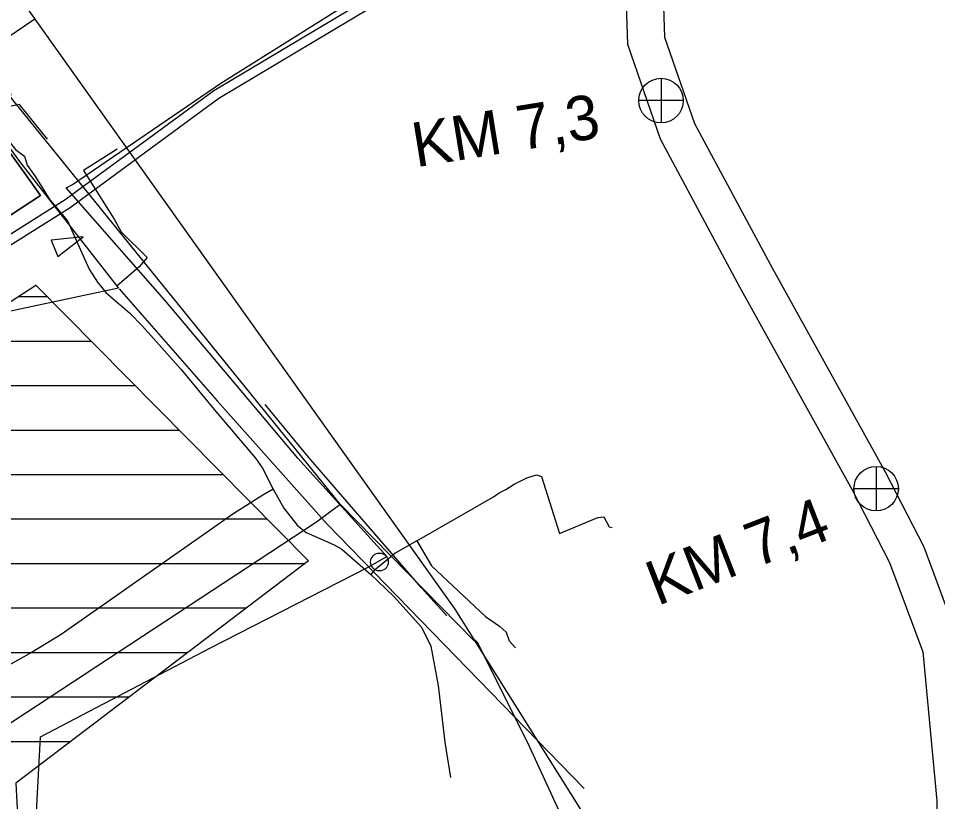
# Model space of a CAD drawing. Extents: x -478232 to -472707, y -1118753 to -1113967.
# Drawn here: x -476775.2 to -476568.7, y -1115764.3 to -1115588.3 of the extents above; entities that cross this region are included whole.
import ezdxf

# ---------------------------------------------------------------- set-up
doc = ezdxf.new("R2010")
doc.units = 0
for name, color, linetype in [('cesty', 7, 'Continuous'), ('el vedeni _VN', 7, 'Continuous'), ('el vedeni_NN', 7, 'Continuous'), ('meliorace', 7, 'Continuous'), ('nesmenovane pozemky', 7, 'Continuous'), ('ObPÚ', 7, 'Continuous'), ('plyn_ntl', 7, 'Continuous'), ('staničení toku', 7, 'Continuous'), ('telekomunikační kabel_O2', 7, 'Continuous'), ('VAK_kanalizace', 7, 'Continuous'), ('VAK_vodovod', 7, 'Continuous'), ('VAK_vodovod_přípojky', 7, 'Continuous'), ('vodní plochy', 7, 'Continuous'), ('Vrstevnice_vedlejsi', 7, 'Continuous')]:
    doc.layers.add(name, color=color, linetype=linetype)

msp = doc.modelspace()

# ---------------------------------------------------------------- linework, layer by layer
at = {"layer": 'cesty'}
msp.add_line((-476767.802, -1115638.116), (-476766.323, -1115641.832), dxfattribs=at)
msp.add_lwpolyline([(-476766.323, -1115641.832), (-476760.608, -1115637.405), (-476767.802, -1115638.116)], dxfattribs=at)
msp.add_circle((-476694.085, -1115710.466), 2, dxfattribs=at)
at = {"layer": 'el vedeni _VN'}
msp.add_lwpolyline([(-476752.99, -1115617.645), (-476760.59, -1115622.439), (-476753.68, -1115633.389), (-476752.07, -1115636.279), (-476746.28, -1115641.999), (-476748.07, -1115644.089), (-476753.11, -1115648.49), (-476752.713, -1115648.935)], dxfattribs=at)
at = {"layer": 'el vedeni_NN'}
for points in [[(-476842.746, -1115543.945), (-476826.67, -1115539.41), (-476812.925, -1115568.597), (-476794.56, -1115593.64), (-476774.96, -1115620.42), (-476752.697, -1115648.952), (-476789.33, -1115656.72), (-476825.27, -1115681.966), (-476857.812, -1115702.761), (-476874.3, -1115755.055)], [(-476752.574, -1115649.093), (-476730.57, -1115674.25), (-476705.81, -1115701.99), (-476648.091, -1115761.403)]]:
    msp.add_lwpolyline(points, dxfattribs=at)
at = {"layer": 'meliorace'}
for p, q in [((-476775.177, -1115650.794), (-476768.78, -1115650.794)), ((-476790.636, -1115660.794), (-476758.887, -1115660.794)), ((-476806.095, -1115670.794), (-476748.994, -1115670.794)), ((-476821.943, -1115680.794), (-476739.101, -1115680.794)), ((-476838.134, -1115690.794), (-476729.208, -1115690.794)), ((-476854.326, -1115700.794), (-476719.315, -1115700.794)), ((-476870.517, -1115710.794), (-476710.772, -1115710.794)), ((-476887.057, -1115720.794), (-476723.945, -1115720.794)), ((-476904.288, -1115730.794), (-476737.118, -1115730.794)), ((-476919.019, -1115740.794), (-476750.29, -1115740.794)), ((-476932.733, -1115750.794), (-476763.463, -1115750.794))]:
    msp.add_line(p, q, dxfattribs=at)
msp.add_lwpolyline([(-476813.359, -1115675.493), (-476771.276, -1115648.271), (-476710.001, -1115710.209), (-476775.799, -1115760.159), (-476774.472, -1115784.378), (-476739.301, -1115887.796), (-476708.136, -1115991.912), (-476722.792, -1115995.923), (-476695.35, -1116044.873), (-476818.693, -1116112.057)], dxfattribs=at)
at = {"layer": 'nesmenovane pozemky'}
for points in [[(-476792.25, -1115597.59), (-476773.71, -1115623.21), (-476770.21, -1115628.06), (-476787.44, -1115639.3)], [(-476787.44, -1115639.3), (-476770.21, -1115628.06), (-476773.71, -1115623.21), (-476792.25, -1115597.59)]]:
    msp.add_lwpolyline(points, dxfattribs=at)
at = {"layer": 'ObPÚ'}
msp.add_lwpolyline([(-476755.544, -1115798.967), (-476755.79, -1115797.97), (-476764.44, -1115799.55), (-476770.52, -1115780.17), (-476771.02, -1115765.24), (-476770.22, -1115749.72), (-476741.776, -1115734.824), (-476732.03, -1115729.72), (-476696.78, -1115711.69), (-476692.45, -1115709.23), (-476710.39, -1115689.36), (-476712.42, -1115687.12), (-476720, -1115678.12), (-476742.31, -1115651.59), (-476761.19, -1115630.08), (-476764.44, -1115626.38), (-476763.03, -1115625.58), (-476729.68, -1115602.85), (-476697.22, -1115582.39)], dxfattribs=at)
at = {"layer": 'plyn_ntl'}
for points in [[(-476768.62, -1115615.425), (-476774.967, -1115607.61), (-476777.83, -1115608.24), (-476776.827, -1115605.311), (-476785.143, -1115595.032), (-476786.55, -1115596.24), (-476786.97, -1115595.69), (-476787.43, -1115594.65), (-476786.145, -1115593.792), (-476796.003, -1115581.607), (-476800.611, -1115575.284), (-476799.879, -1115572.693), (-476800.947, -1115571.002), (-476803.485, -1115571.341), (-476826.742, -1115538.926), (-476844.672, -1115531.409), (-476847.418, -1115530.475)], [(-476678.906, -1115722.55), (-476684.652, -1115716.251), (-476709.926, -1115687.011), (-476719.738, -1115675.069)]]:
    msp.add_lwpolyline(points, dxfattribs=at)
at = {"layer": 'staničení toku'}
for p, q in [((-476630.813, -1115601.754), (-476630.813, -1115611.754)), ((-476625.813, -1115606.754), (-476635.813, -1115606.754)), ((-476582.486, -1115688.979), (-476582.486, -1115698.979)), ((-476577.486, -1115693.979), (-476587.486, -1115693.979))]:
    msp.add_line(p, q, dxfattribs=at)
for centre in [(-476630.813, -1115606.754), (-476582.486, -1115693.979)]:
    msp.add_circle(centre, 5, dxfattribs=at)
at = {"layer": 'telekomunikační kabel_O2'}
for points in [[(-476795.86, -1115590.93), (-476793.46, -1115592.37), (-476792.94, -1115594.42), (-476787.13, -1115602.51), (-476786.27, -1115604.1), (-476781.16, -1115611.21), (-476775.83, -1115617.77), (-476773.83, -1115619.24), (-476773.21, -1115621.26), (-476771.36, -1115623.91), (-476768.11, -1115629.05), (-476766.84, -1115630.54), (-476764.19, -1115633.77), (-476759.3, -1115644.62), (-476757.44, -1115647.57), (-476755.47, -1115649.96), (-476750.24, -1115654.43), (-476747.33, -1115657.43), (-476738.59, -1115667.17), (-476731.2, -1115676.2), (-476721.89, -1115687.13), (-476720.36, -1115689.36), (-476717.92, -1115694.08)], [(-476685.69, -1115705.74), (-476668.46, -1115695.81), (-476667.16, -1115694.95), (-476665.66, -1115694.15), (-476663.84, -1115692.93), (-476660.95, -1115691.56), (-476658.81, -1115690.9), (-476657.64, -1115691.22), (-476653.59, -1115704.04), (-476645.01, -1115700.43), (-476643.67, -1115700.34), (-476642.43, -1115702.52), (-476641.77, -1115702.7)], [(-476717.92, -1115694.08), (-476720.31, -1115695.41), (-476726.82, -1115699.56), (-476765.59, -1115726.76), (-476772.12, -1115730.76), (-476777.23, -1115733.55), (-476814.59, -1115755.33), (-476823.08, -1115763.59), (-476832.29, -1115773.13), (-476834.57, -1115777.72), (-476837.05, -1115781.43), (-476838.36, -1115783.59)], [(-476717.92, -1115694.08), (-476715.59, -1115698.34), (-476712.58, -1115702.18), (-476710.53, -1115703.8), (-476704.24, -1115706.58), (-476702.51, -1115707.57), (-476695.98, -1115713.3)], [(-476685.69, -1115705.74), (-476690.51, -1115708.46), (-476691.58, -1115709.41), (-476695.28, -1115712.34), (-476695.98, -1115713.3)], [(-476685.69, -1115705.74), (-476682.42, -1115711.33), (-476670.27, -1115722.69), (-476667.14, -1115724.87), (-476665.63, -1115726.21), (-476664.95, -1115728.18), (-476663.54, -1115729.78)], [(-476695.98, -1115713.3), (-476690.87, -1115718.25), (-476684.61, -1115725.07), (-476682.55, -1115729.41), (-476680.87, -1115738.2), (-476679.36, -1115750.92), (-476678.12, -1115758.87)]]:
    msp.add_lwpolyline(points, dxfattribs=at)
at = {"layer": 'VAK_kanalizace'}
for points in [[(-476596.91, -1115841.27), (-476639.491, -1115781.004), (-476677.085, -1115721.078), (-476807.031, -1115538.469)], [(-476894.404, -1115671.748), (-476771.514, -1115588.381)]]:
    msp.add_lwpolyline(points, dxfattribs=at)
at = {"layer": 'VAK_vodovod'}
for points in [[(-476672.829, -1115728.19), (-476702.929, -1115697.489), (-476776.53, -1115606.54), (-476784.5, -1115595.84), (-476802.579, -1115571.44), (-476814.96, -1115553.93), (-476816.319, -1115551.759), (-476816.39, -1115551.679), (-476816.539, -1115551.549)], [(-476597.42, -1115847.819), (-476597.5, -1115847.629), (-476609.099, -1115828.549), (-476636.19, -1115792.68), (-476641.09, -1115787.7), (-476646.199, -1115782.6), (-476646.3, -1115782.469), (-476660.829, -1115750.93), (-476672.039, -1115728.579), (-476672.619, -1115727.94), (-476672.81, -1115728.211), (-476672.829, -1115728.19)]]:
    msp.add_lwpolyline(points, dxfattribs=at)
at = {"layer": 'VAK_vodovod_přípojky'}
msp.add_lwpolyline([(-476702.929, -1115697.489), (-476703.01, -1115697.59), (-476708.23, -1115701.54), (-476836.062, -1115785.486)], dxfattribs=at)
at = {"layer": 'vodní plochy'}
for points in [[(-476638.113, -1115553.904), (-476643.882, -1115556.28), (-476692.746, -1115581.454), (-476731.259, -1115604.531), (-476764.657, -1115629.099), (-476802.386, -1115652.775), (-476819.266, -1115663.622), (-476873.466, -1115698.453), (-476876.962, -1115700.938), (-476893.934, -1115713.636)], [(-476818.184, -1115665.304), (-476801.314, -1115654.463), (-476763.531, -1115630.753), (-476730.149, -1115606.199), (-476691.774, -1115583.202), (-476643.042, -1115558.096), (-476638.192, -1115556.1)], [(-476638.918, -1115576.256), (-476638.355, -1115594.111), (-476631.011, -1115615.36), (-476613.159, -1115648.596), (-476587.847, -1115694.272), (-476579.484, -1115710.554), (-476572.024, -1115730.684), (-476568.86, -1115764.155), (-476569.538, -1115796.945), (-476573.154, -1115833.122), (-476573.38, -1115858.669), (-476569.313, -1115885.12)], [(-476561.038, -1115883.278), (-476564.915, -1115858.06), (-476564.699, -1115833.581), (-476561.088, -1115797.453), (-476560.393, -1115763.843), (-476563.707, -1115728.784), (-476571.729, -1115707.14), (-476580.384, -1115690.288), (-476605.733, -1115644.544), (-476623.238, -1115611.955), (-476629.941, -1115592.562), (-476630.454, -1115576.275)]]:
    msp.add_lwpolyline(points, dxfattribs=at)
at = {"layer": 'Vrstevnice_vedlejsi'}
for points in [[(-476765.232, -1115950.68), (-476768.635, -1115941.359), (-476771.601, -1115933.808), (-476774.129, -1115928.026), (-476776.22, -1115924.013), (-476777.972, -1115919.286), (-476779.386, -1115913.846), (-476780.463, -1115907.693), (-476783.231, -1115902.898), (-476787.693, -1115899.461), (-476793.846, -1115897.383), (-476799.718, -1115894.297), (-476805.309, -1115890.204), (-476810.617, -1115885.102), (-476816.831, -1115878.775), (-476823.951, -1115871.224), (-476831.975, -1115862.448), (-476838.218, -1115855.08), (-476842.677, -1115849.118), (-476845.355, -1115844.563), (-476849.062, -1115837.384), (-476853.798, -1115827.581), (-476859.563, -1115815.153), (-476863.515, -1115806.728), (-476865.653, -1115802.304), (-476865.978, -1115801.882), (-476866.162, -1115801.565), (-476866.206, -1115801.352), (-476866.111, -1115801.245), (-476866.068, -1115801.121), (-476866.077, -1115800.981), (-476866.139, -1115800.826), (-476867.724, -1115798.235), (-476870.834, -1115793.208), (-476875.467, -1115785.746), (-476879.116, -1115780.289), (-476881.782, -1115776.838), (-476883.464, -1115775.392), (-476886.105, -1115772.851), (-476889.705, -1115769.216), (-476894.264, -1115764.487), (-476898.706, -1115759.072), (-476903.029, -1115752.972), (-476907.235, -1115746.186), (-476910.642, -1115741.194), (-476913.25, -1115737.996), (-476915.059, -1115736.591), (-476916.37, -1115735.556), (-476917.182, -1115734.891), (-476917.495, -1115734.596), (-476917.73, -1115734.3), (-476917.886, -1115734.003), (-476917.963, -1115733.706), (-476918.084, -1115733.385), (-476918.249, -1115733.04), (-476918.458, -1115732.672), (-476919, -1115731.221), (-476919.876, -1115728.689), (-476921.085, -1115725.074), (-476922.197, -1115722.333), (-476923.212, -1115720.464), (-476924.13, -1115719.468), (-476925.018, -1115718.454), (-476925.874, -1115717.423), (-476926.701, -1115716.374), (-476927.413, -1115715.574), (-476928.011, -1115715.022), (-476928.496, -1115714.719), (-476928.752, -1115713.957), (-476928.779, -1115712.734), (-476928.578, -1115711.051), (-476928.475, -1115709.892), (-476928.472, -1115709.256), (-476928.569, -1115709.144), (-476928.659, -1115709.026), (-476928.742, -1115708.9), (-476928.819, -1115708.767), (-476929.107, -1115708.172), (-476929.607, -1115707.115), (-476930.318, -1115705.596), (-476930.876, -1115704.442), (-476931.281, -1115703.653), (-476931.531, -1115703.231), (-476931.893, -1115702.616), (-476932.367, -1115701.808), (-476932.951, -1115700.808), (-476933.519, -1115699.983), (-476934.071, -1115699.331), (-476934.606, -1115698.854), (-476935.124, -1115698.369), (-476935.624, -1115697.876), (-476936.106, -1115697.375), (-476936.698, -1115696.799), (-476937.4, -1115696.148), (-476938.212, -1115695.422), (-476938.943, -1115694.713), (-476939.594, -1115694.023)], [(-476760.309, -1115922.621), (-476760.619, -1115921.775), (-476760.878, -1115921.107), (-476761.089, -1115920.619), (-476761.25, -1115920.309), (-476761.996, -1115916.454), (-476763.326, -1115909.052), (-476765.241, -1115898.104), (-476768.872, -1115890.01), (-476774.22, -1115884.77), (-476781.284, -1115882.385), (-476786.446, -1115879.954), (-476789.707, -1115877.475), (-476791.066, -1115874.951), (-476792.814, -1115873.183), (-476794.951, -1115872.171), (-476797.475, -1115871.916), (-476802.154, -1115868.229), (-476808.987, -1115861.108), (-476817.975, -1115850.554), (-476824.428, -1115842.713), (-476828.348, -1115837.584), (-476829.735, -1115835.168), (-476830.854, -1115833.384), (-476831.706, -1115832.231), (-476832.291, -1115831.709), (-476832.904, -1115831.275), (-476833.544, -1115830.927), (-476834.212, -1115830.665), (-476834.845, -1115829.575), (-476835.443, -1115827.656), (-476836.005, -1115824.907), (-476836.546, -1115822.913), (-476837.067, -1115821.673), (-476837.567, -1115821.188), (-476838.198, -1115819.989), (-476838.961, -1115818.079), (-476839.855, -1115815.456), (-476840.607, -1115812.288), (-476841.217, -1115808.577), (-476841.685, -1115804.321), (-476842.285, -1115800.103), (-476843.015, -1115795.923), (-476843.876, -1115791.78), (-476846.033, -1115787.218), (-476849.486, -1115782.239), (-476854.234, -1115776.84), (-476859.483, -1115771.888), (-476865.232, -1115767.382), (-476871.482, -1115763.322), (-476875.748, -1115760.389), (-476878.03, -1115758.582), (-476878.328, -1115757.902), (-476878.568, -1115757.35), (-476878.75, -1115756.925), (-476878.875, -1115756.629), (-476879.002, -1115756.301), (-476879.132, -1115755.942), (-476879.265, -1115755.552), (-476879.374, -1115755.119), (-476879.458, -1115754.643), (-476879.519, -1115754.124), (-476880.12, -1115751.501), (-476881.261, -1115746.774), (-476882.942, -1115739.943), (-476884.416, -1115735.179), (-476885.681, -1115732.482), (-476886.738, -1115731.853), (-476887.509, -1115731.223), (-476887.995, -1115730.592), (-476888.195, -1115729.96), (-476888.375, -1115729.231), (-476888.535, -1115728.405), (-476888.675, -1115727.482), (-476889.655, -1115726.012), (-476891.475, -1115723.995), (-476894.134, -1115721.433), (-476895.906, -1115719.719), (-476896.79, -1115718.853), (-476896.787, -1115718.836), (-476896.783, -1115718.822), (-476896.779, -1115718.811), (-476896.774, -1115718.804), (-476897.024, -1115718.807), (-476897.529, -1115718.82), (-476898.29, -1115718.843), (-476899.009, -1115718.866), (-476899.685, -1115718.89), (-476900.318, -1115718.914), (-476900.536, -1115718.893), (-476900.337, -1115718.829), (-476899.722, -1115718.719), (-476899.276, -1115718.636), (-476899, -1115718.579), (-476898.894, -1115718.548), (-476898.538, -1115718.364), (-476897.933, -1115718.027)], [(-476956.451, -1115757.96), (-476955.947, -1115758.905), (-476955.33, -1115759.819), (-476954.599, -1115760.704), (-476953.754, -1115761.558), (-476949.534, -1115765.772), (-476941.939, -1115773.344), (-476930.969, -1115784.274), (-476923.069, -1115792.224), (-476918.239, -1115797.194), (-476916.478, -1115799.183), (-476915.178, -1115800.784), (-476914.34, -1115801.999), (-476913.964, -1115802.827), (-476913.577, -1115803.694), (-476913.178, -1115804.601), (-476912.769, -1115805.546), (-476912.742, -1115806.333), (-476913.098, -1115806.962), (-476913.836, -1115807.433), (-476914.363, -1115807.763), (-476914.677, -1115807.952), (-476914.779, -1115808), (-476914.83, -1115808.049), (-476914.83, -1115808.099), (-476914.78, -1115808.15), (-476914.505, -1115808.68), (-476914.005, -1115809.689), (-476913.281, -1115811.176), (-476912.486, -1115812.224), (-476911.621, -1115812.833), (-476910.686, -1115813.002), (-476909.935, -1115813.191), (-476909.368, -1115813.398), (-476908.985, -1115813.623), (-476908.355, -1115814.308), (-476907.478, -1115815.453), (-476906.354, -1115817.057), (-476903.756, -1115820.502), (-476899.685, -1115825.786), (-476894.14, -1115832.91), (-476890.075, -1115838.248), (-476887.489, -1115841.8), (-476886.384, -1115843.566), (-476885.059, -1115845.602), (-476883.515, -1115847.908), (-476881.751, -1115850.483), (-476878.917, -1115855.2), (-476875.012, -1115862.057), (-476870.036, -1115871.055), (-476863.934, -1115880.778), (-476856.707, -1115891.224), (-476848.353, -1115902.396), (-476842.042, -1115910.558), (-476837.771, -1115915.711), (-476835.543, -1115917.856), (-476832.951, -1115921.134), (-476829.995, -1115925.548), (-476826.676, -1115931.095), (-476823.02, -1115937.394), (-476819.027, -1115944.444), (-476814.697, -1115952.245), (-476811.794, -1115960.752), (-476810.318, -1115969.966), (-476810.27, -1115979.887), (-476809.908, -1115987.633), (-476809.231, -1115993.205), (-476808.239, -1115996.603), (-476807.476, -1115999.571), (-476806.943, -1116002.109), (-476806.639, -1116004.218), (-476805.733, -1116006.161), (-476804.224, -1116007.937), (-476802.112, -1116009.548), (-476799.049, -1116012.171), (-476795.035, -1116015.808), (-476790.071, -1116020.457), (-476784.378, -1116025.211), (-476777.957, -1116030.071), (-476770.808, -1116035.035), (-476765.689, -1116038.851), (-476762.598, -1116041.517), (-476761.537, -1116043.033), (-476759.81, -1116046.085), (-476757.418, -1116050.672), (-476754.36, -1116056.794), (-476751.836, -1116061.346), (-476749.844, -1116064.327), (-476748.386, -1116065.738), (-476746.639, -1116068.106), (-476744.602, -1116071.433), (-476742.275, -1116075.716), (-476740.537, -1116079.586), (-476739.577, -1116082.33)]]:
    msp.add_spline(points, degree=3, dxfattribs=at)

# ---------------------------------------------------------------- texts
at = {"layer": 'staničení toku'}
for s, rotation, p in [('KM 7,3', 9.17265, (-476685.874, -1115621.766)), ('KM 7,4', 21.21906, (-476631.616, -1115720.375))]:
    msp.add_text(s, height=10, rotation=rotation, dxfattribs=at).set_placement(p)

doc.saveas('drawing.dxf')
